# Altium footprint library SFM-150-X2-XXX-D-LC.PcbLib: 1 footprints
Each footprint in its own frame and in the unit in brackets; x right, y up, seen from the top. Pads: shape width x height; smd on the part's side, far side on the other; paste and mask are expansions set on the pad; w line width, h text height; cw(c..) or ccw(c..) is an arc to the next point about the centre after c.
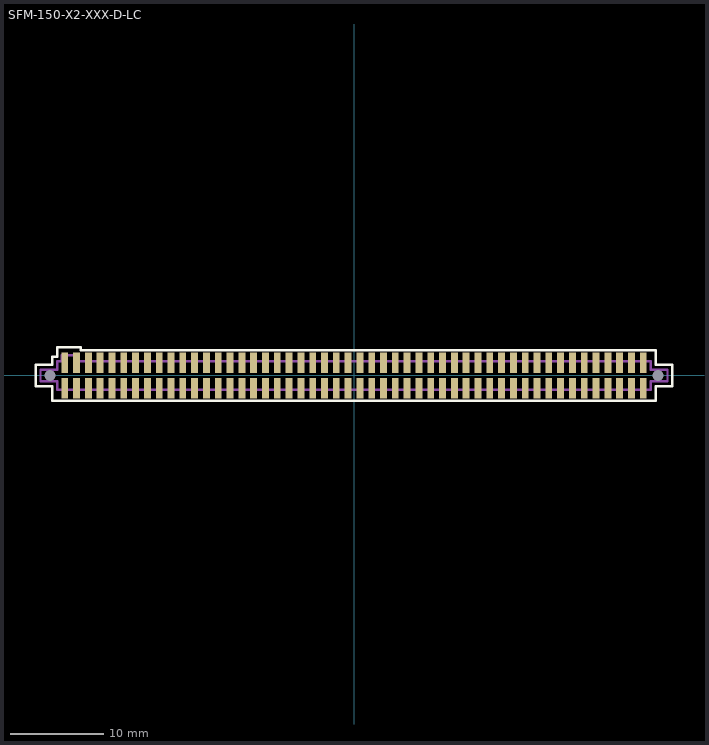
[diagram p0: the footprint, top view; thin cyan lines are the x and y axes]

## SFM-150-X2-XXX-D-LC [mil]
pads (102):
  rect 29x87.5 smd mask+2: 1(1225,-53.75) 2(1225,53.75) 3(1175,-53.75) 4(1175,53.75) 5(1125,-53.75) 6(1125,53.75) 7(1075,-53.75) 8(1075,53.75) 9(1025,-53.75) 10(1025,53.75) 11(975,-53.75) 12(975,53.75) 13(925,-53.75) 14(925,53.75) 15(875,-53.75) 16(875,53.75) 17(825,-53.75) 18(825,53.75) 19(775,-53.75) 20(775,53.75) 21(725,-53.75) 22(725,53.75) 23(675,-53.75) 24(675,53.75) 25(625,-53.75) 26(625,53.75) 27(575,-53.75) 28(575,53.75) 29(525,-53.75) 30(525,53.75) 31(475,-53.75) 32(475,53.75) 33(425,-53.75) 34(425,53.75) 35(375,-53.75) 36(375,53.75) 37(325,-53.75) 38(325,53.75) 39(275,-53.75) 40(275,53.75) 41(225,-53.75) 42(225,53.75) 43(175,-53.75) 44(175,53.75) 45(125,-53.75) 46(125,53.75) 47(75,-53.75) 48(75,53.75) 49(25,-53.75) 50(25,53.75) 51(-25,-53.75) 52(-25,53.75) 53(-75,-53.75) 54(-75,53.75) 55(-125,-53.75) 56(-125,53.75) 57(-175,-53.75) 58(-175,53.75) 59(-225,-53.75) 60(-225,53.75) 61(-275,-53.75) 62(-275,53.75) 63(-325,-53.75) 64(-325,53.75) 65(-375,-53.75) 66(-375,53.75) 67(-425,-53.75) 68(-425,53.75) 69(-475,-53.75) 70(-475,53.75) 71(-525,-53.75) 72(-525,53.75) 73(-575,-53.75) 74(-575,53.75) 75(-625,-53.75) 76(-625,53.75) 77(-675,-53.75) 78(-675,53.75) 79(-725,-53.75) 80(-725,53.75) 81(-775,-53.75) 82(-775,53.75) 83(-825,-53.75) 84(-825,53.75) 85(-875,-53.75) 86(-875,53.75) 87(-925,-53.75) 88(-925,53.75) 89(-975,-53.75) 90(-975,53.75) 91(-1025,-53.75) 92(-1025,53.75) 93(-1075,-53.75) 94(-1075,53.75) 95(-1125,-53.75) 96(-1125,53.75) 97(-1175,-53.75) 98(-1175,53.75) 99(-1225,-53.75) 100(-1225,53.75)
  round 0 / inner rrect0% 0x0 / far side rrect0% 0x0 hole 47 unplated: 101(1287.5,0) 102(-1287.5,0)
Top Overlay:
  lines w10: -1347.5,-45 -1277.5,-45 -1277.5,-107.5 1277.5,-107.5 1277.5,-45 1347.5,-45 1347.5,45 1277.5,45 1277.5,107.5 -1157.5,107.5 -1157.5,120 -1257.5,120 -1257.5,80 -1277.5,80 -1277.5,45 -1347.5,45 -1347.5,-45
Mechanical 1:
  lines w10: -1327.5,-25 -1257.5,-25 -1257.5,-60 1257.5,-60 1257.5,-25 1327.5,-25 1327.5,25 1257.5,25 1257.5,60 -1177.5,60 -1177.5,85 -1237.5,85 -1237.5,60 -1257.5,60 -1257.5,25 -1327.5,25 -1327.5,-25
  text "J1" at -17.57,-18 h30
